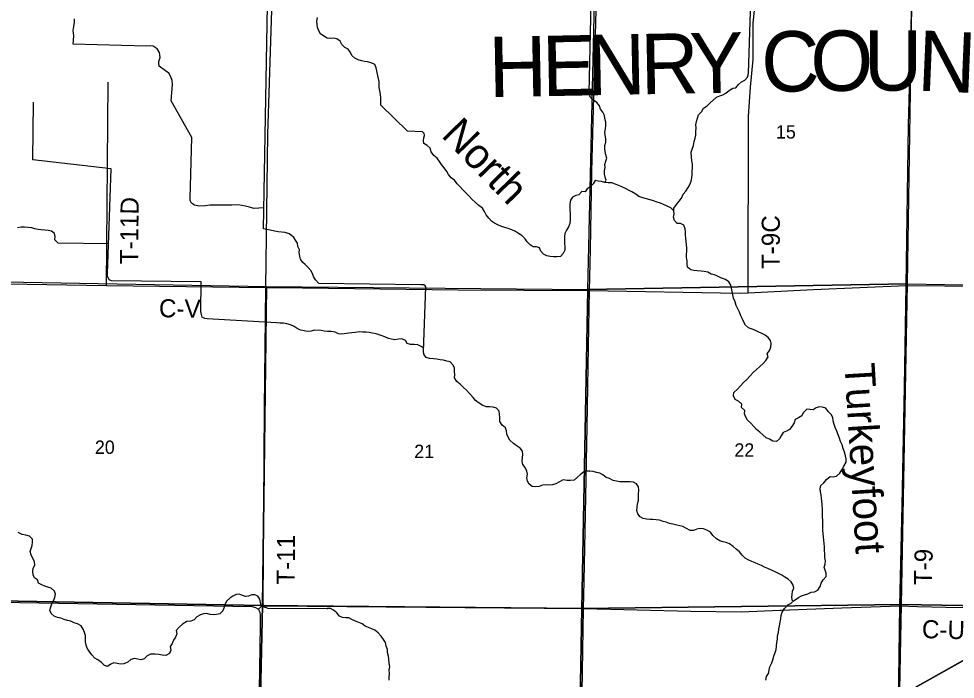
# Model space of a CAD drawing. Extents: x -6.2 to 37.4, y 0.2 to 22.2.
# Drawn here: x 3.568 to 5.038, y 19.239 to 20.275 of the extents above; entities that cross this region are included whole.
import ezdxf

# ---------------------------------------------------------------- set-up
doc = ezdxf.new("R2010")
doc.units = 0
for name, color, linetype in [('GM_X_County_Road', 7, 'Continuous'), ('GM_X_County_Road_Text', 7, 'Continuous'), ('GM_X_County_Text', 7, 'Continuous'), ('GM_X_Minor_River', 7, 'Continuous'), ('GM_X_Minor_River_Text', 7, 'Continuous'), ('GM_X_Section', 7, 'Continuous'), ('GM_X_Section_Text', 7, 'Continuous'), ('GM_X_Township_Road', 7, 'Continuous'), ('GM_X_Township_Road_Text', 7, 'Continuous'), ('SH_Border', 7, 'Continuous'), ('SH_Data', 7, 'Continuous')]:
    doc.layers.add(name, color=color, linetype=linetype)

msp = doc.modelspace()

# ---------------------------------------------------------------- linework, layer by layer
at = {"layer": 'GM_X_County_Road'}
for points in [[(2.9584, 19.8774), (3.2306, 19.8655), (3.4561, 19.861), (3.7061, 19.8569), (3.956, 19.8537), (3.9729, 19.8535), (4.2583, 19.8498), (4.4643, 19.8487)], [(4.4643, 19.8487), (4.6989, 19.8446), (4.7131, 19.8453), (4.8157, 19.8502), (4.9612, 19.8569), (5.0809, 19.8554)], [(4.9421, 18.8443), (4.9484, 19.1615), (4.9514, 19.3541)], [(4.9514, 19.3541), (4.9789, 19.3528), (5.0234, 19.3518), (5.0805, 19.3507), (5.0809, 19.3507)]]:
    msp.add_lwpolyline(points, dxfattribs=at)
at = {"layer": 'GM_X_Minor_River'}
for points in [[(4.2038, 19.7539), (4.2074, 19.8544), (4.2061, 19.8561), (4.2041, 19.8575), (4.1997, 19.8578), (4.0393, 19.8599), (4.0339, 19.8657), (4.0308, 19.871), (4.0292, 19.8756), (4.0266, 19.8804), (4.0224, 19.8851), (4.0177, 19.8895), (4.0144, 19.8928), (4.0107, 19.8982), (4.0093, 19.9024), (4.0087, 19.9091), (4.0088, 19.9128), (4.0066, 19.918), (4.0061, 19.9233), (4.0026, 19.9278), (3.9999, 19.932), (3.9967, 19.9353), (3.9926, 19.9376), (3.9864, 19.9397), (3.9755, 19.941), (3.9527, 19.9458), (3.9597, 20.3549)], [(4.4634, 20.1588), (4.468, 20.348)], [(4.7137, 20.1892), (4.719, 20.3522)], [(3.9532, 19.9785), (3.9376, 19.9775), (3.9307, 19.9795), (3.9243, 19.9809), (3.9129, 19.9831), (3.9029, 19.9827), (3.8912, 19.9826), (3.8792, 19.9826), (3.8681, 19.9826), (3.8616, 19.9818), (3.8514, 19.9809), (3.844, 19.9827), (3.8396, 19.9857), (3.8376, 19.9901), (3.8373, 19.9933), (3.84, 20.0887), (3.8077, 20.1464), (3.8096, 20.1718), (3.809, 20.1781), (3.8072, 20.184), (3.8037, 20.1896), (3.7985, 20.1937), (3.7888, 20.2009), (3.7883, 20.2053), (3.7884, 20.2079), (3.7904, 20.2143), (3.7894, 20.2225), (3.7858, 20.2281), (3.7796, 20.232), (3.7736, 20.2329), (3.7681, 20.232), (3.654, 20.2355), (3.6545, 20.2415), (3.6547, 20.2483), (3.6539, 20.2567), (3.6546, 20.263), (3.6559, 20.2696), (3.656, 20.2753)], [(4.1294, 20.1984), (4.1271, 20.2032), (4.1216, 20.2059), (4.116, 20.2074), (4.1111, 20.2079), (4.1062, 20.2091), (4.1013, 20.2105), (4.0961, 20.2131), (4.091, 20.2174), (4.0889, 20.2223), (4.0852, 20.2277), (4.0803, 20.2299), (4.0755, 20.235), (4.0731, 20.2399), (4.0677, 20.2438), (4.0626, 20.2445), (4.0572, 20.2444), (4.0522, 20.2449), (4.047, 20.2477), (4.0418, 20.2518), (4.0392, 20.2565), (4.0373, 20.2615), (4.0366, 20.2668), (4.0361, 20.2716), (4.0374, 20.2773)], [(4.2037, 20.0844), (4.2039, 20.0885), (4.205, 20.0921), (4.2045, 20.095), (4.2036, 20.0963), (4.2019, 20.0979), (4.1783, 20.0986), (4.1367, 20.1396), (4.1366, 20.1504), (4.136, 20.1569), (4.1343, 20.1674), (4.1343, 20.1763), (4.1294, 20.1984)], [(4.5964, 19.9738), (4.5967, 19.978), (4.6006, 19.984), (4.6051, 19.989), (4.6086, 19.9939), (4.6113, 19.9999), (4.6154, 20.0049), (4.6191, 20.0102), (4.6217, 20.0154), (4.6235, 20.0205), (4.6249, 20.0254), (4.6254, 20.0305), (4.6253, 20.0356), (4.6258, 20.0415), (4.626, 20.0472), (4.6249, 20.0525), (4.6245, 20.0579), (4.6239, 20.0658), (4.6255, 20.0707), (4.6275, 20.0764), (4.6286, 20.0826), (4.6302, 20.0879), (4.6311, 20.0928), (4.6312, 20.0983), (4.6315, 20.104), (4.6312, 20.1087), (4.6323, 20.1142), (4.6335, 20.1191), (4.6355, 20.1242), (4.64, 20.1294), (4.6431, 20.1347), (4.6487, 20.1386), (4.6537, 20.1434), (4.6637, 20.1523), (4.6689, 20.1541), (4.6737, 20.1559), (4.6784, 20.1584), (4.6837, 20.1629), (4.689, 20.1662), (4.6938, 20.1667), (4.698, 20.1721), (4.7029, 20.176), (4.7078, 20.1787), (4.7123, 20.1836), (4.7137, 20.1892)], [(4.4883, 20.0185), (4.4901, 20.0219), (4.4889, 20.0268), (4.4877, 20.0316), (4.4878, 20.0365), (4.4886, 20.0418), (4.4885, 20.0466), (4.4896, 20.0519), (4.4916, 20.0567), (4.4896, 20.0619), (4.4886, 20.0669), (4.4881, 20.0718), (4.488, 20.0765), (4.49, 20.0816), (4.4896, 20.0866), (4.4887, 20.0925), (4.4881, 20.0972), (4.4891, 20.1025), (4.4898, 20.1076), (4.4899, 20.1131), (4.4885, 20.1186), (4.4877, 20.1236), (4.4853, 20.1284), (4.4816, 20.1334), (4.4797, 20.1384), (4.4756, 20.1436), (4.4706, 20.1475), (4.4656, 20.1519), (4.4638, 20.1569), (4.4634, 20.1588)], [(3.9729, 19.7982), (3.8642, 19.8044), (3.8602, 19.8051), (3.8561, 19.8068), (3.855, 19.811), (3.8542, 19.8158), (3.8548, 19.8623), (3.7138, 19.8638), (3.7104, 19.8657), (3.7079, 19.8713), (3.7078, 19.8755), (3.7133, 20.0398), (3.5904, 20.0539), (3.5913, 20.1443)], [(4.4574, 20.0038), (4.4524, 20.0044), (4.4474, 19.9988), (4.4425, 19.998), (4.4373, 19.9954), (4.4342, 19.9904), (4.4333, 19.9849), (4.4332, 19.9798), (4.4335, 19.975), (4.4336, 19.9703), (4.434, 19.965), (4.4337, 19.9595), (4.4332, 19.954), (4.4314, 19.9485), (4.4281, 19.9436), (4.4255, 19.9384), (4.4248, 19.9331), (4.4247, 19.9282), (4.4252, 19.9228), (4.4254, 19.9173), (4.4255, 19.912), (4.4228, 19.9071), (4.4185, 19.9023), (4.4128, 19.9017), (4.4079, 19.9018), (4.4024, 19.9021), (4.3971, 19.9033), (4.3919, 19.9057), (4.388, 19.9107), (4.3859, 19.916), (4.381, 19.9175), (4.376, 19.9174), (4.371, 19.9203), (4.3666, 19.9252), (4.3631, 19.93), (4.3582, 19.935), (4.3526, 19.9382), (4.3478, 19.9413), (4.3422, 19.9441), (4.3363, 19.9463), (4.3311, 19.9479), (4.3258, 19.9493), (4.3204, 19.9521), (4.3153, 19.9547), (4.3103, 19.9576), (4.306, 19.9624), (4.3018, 19.9676), (4.2992, 19.9726), (4.2961, 19.978), (4.2907, 19.9823), (4.285, 19.9871), (4.2794, 19.992), (4.2751, 19.997), (4.2707, 20.0018), (4.2653, 20.0067), (4.2614, 20.0115), (4.2564, 20.0164), (4.2524, 20.0219), (4.2471, 20.0258), (4.2431, 20.0307), (4.2402, 20.0357), (4.2361, 20.0411), (4.2317, 20.0465), (4.2286, 20.0514), (4.2253, 20.0563), (4.2201, 20.0609), (4.2156, 20.0665), (4.214, 20.0719), (4.2092, 20.0761), (4.2044, 20.0793), (4.2037, 20.0844)], [(4.7124, 19.6454), (4.7093, 19.6502), (4.7075, 19.6552), (4.7081, 19.6605), (4.7029, 19.6655), (4.7032, 19.6704), (4.6978, 19.6751), (4.6926, 19.678), (4.6903, 19.6834), (4.6908, 19.6889), (4.6964, 19.6941), (4.7012, 19.6993), (4.7058, 19.7043), (4.7109, 19.709), (4.7161, 19.7149), (4.7208, 19.7202), (4.7258, 19.7244), (4.7314, 19.7296), (4.7368, 19.7342), (4.7412, 19.7391), (4.7447, 19.7445), (4.7431, 19.7497), (4.7465, 19.7545), (4.749, 19.7598), (4.7491, 19.7655), (4.7485, 19.7702), (4.7446, 19.7751), (4.7398, 19.7788), (4.7345, 19.7813), (4.7291, 19.7841), (4.7238, 19.7865), (4.7137, 19.7905), (4.7089, 19.7944), (4.7065, 19.7992), (4.7043, 19.8039), (4.7016, 19.8093), (4.6994, 19.8147), (4.6971, 19.8202), (4.6944, 19.8252), (4.6928, 19.8309), (4.6903, 19.837), (4.6889, 19.8418), (4.688, 19.8475), (4.6872, 19.8525), (4.6861, 19.8572), (4.6827, 19.8622), (4.6774, 19.866), (4.6716, 19.868), (4.6651, 19.8715), (4.6602, 19.8733), (4.6553, 19.8746), (4.6499, 19.8775), (4.6444, 19.8788), (4.6395, 19.8794), (4.6334, 19.8797), (4.628, 19.8802), (4.6231, 19.8813), (4.6182, 19.8852), (4.6174, 19.8903), (4.6173, 19.8954), (4.6166, 19.9008), (4.617, 19.9154), (4.6163, 19.9212), (4.6154, 19.9308), (4.6151, 19.9361), (4.6148, 19.9408), (4.6144, 19.9458), (4.612, 19.9511), (4.6072, 19.9541), (4.6017, 19.954), (4.5976, 19.9588), (4.5962, 19.9641), (4.5971, 19.9691), (4.5964, 19.9738), (4.5916, 19.9787), (4.5862, 19.9814), (4.5805, 19.9838), (4.5757, 19.9858), (4.5704, 19.9876), (4.5646, 19.9896), (4.5593, 19.9909), (4.5536, 19.9925), (4.5478, 19.9941), (4.5418, 19.9964), (4.537, 19.9999), (4.5308, 20.0036), (4.5255, 20.0065), (4.5205, 20.0091), (4.5151, 20.0117), (4.51, 20.0137), (4.5047, 20.0159), (4.4995, 20.0177), (4.4936, 20.018), (4.4883, 20.0185), (4.4829, 20.0197), (4.478, 20.0204), (4.4729, 20.0213), (4.4701, 20.0162), (4.4653, 20.0116), (4.4605, 20.0086), (4.4574, 20.0038)], [(3.6301, 19.9233), (3.6252, 19.9283), (3.6253, 19.9336), (3.6245, 19.9384), (3.6197, 19.9421), (3.6144, 19.9432), (3.6095, 19.9433), (3.6038, 19.9439), (3.5989, 19.9444), (3.5936, 19.9458), (3.5887, 19.9469), (3.5834, 19.9476), (3.5774, 19.9484), (3.5721, 19.9484), (3.5664, 19.947)], [(3.7094, 19.9223), (3.6301, 19.9233)], [(4.204, 19.7586), (4.2002, 19.7612), (4.1947, 19.7636), (4.1892, 19.7641), (4.1832, 19.764), (4.1781, 19.7655), (4.1754, 19.7704), (4.1694, 19.773), (4.1644, 19.7724), (4.1589, 19.7715), (4.1535, 19.7724), (4.1485, 19.7733), (4.1431, 19.776), (4.1373, 19.7782), (4.1292, 19.7807), (4.1237, 19.7819), (4.1185, 19.7828), (4.1136, 19.7836), (4.1079, 19.7834), (4.103, 19.784), (4.0963, 19.7827), (4.0912, 19.7826), (4.0863, 19.7819), (4.0753, 19.7802), (4.07, 19.7811), (4.0651, 19.7833), (4.0589, 19.7844), (4.053, 19.7847), (4.0479, 19.7848), (4.043, 19.7862), (4.0322, 19.7864), (4.0275, 19.7848), (4.0214, 19.7847), (4.0163, 19.7854), (4.0107, 19.7867), (4.0056, 19.7892), (4.0004, 19.7924), (3.9949, 19.7948), (3.9893, 19.7966), (3.9838, 19.7976), (3.9781, 19.7977), (3.9729, 19.7982)], [(4.3589, 19.5867), (4.3596, 19.5916), (4.3591, 19.5966), (4.3552, 19.6016), (4.3504, 19.6045), (4.345, 19.6086), (4.339, 19.6139), (4.3365, 19.6187), (4.3345, 19.6234), (4.3338, 19.6286), (4.3322, 19.6335), (4.3272, 19.6376), (4.3236, 19.6434), (4.3237, 19.6498), (4.323, 19.6548), (4.3222, 19.6595), (4.3183, 19.6644), (4.3129, 19.666), (4.3078, 19.6663), (4.3023, 19.6662), (4.297, 19.6684), (4.2908, 19.6719), (4.2853, 19.676), (4.2814, 19.6809), (4.276, 19.6874), (4.271, 19.6924), (4.2662, 19.6967), (4.261, 19.7017), (4.256, 19.7058), (4.2521, 19.7116), (4.2526, 19.7165), (4.2523, 19.7218), (4.2522, 19.7268), (4.2503, 19.7317), (4.2456, 19.7368), (4.2402, 19.7382), (4.2349, 19.7395), (4.2296, 19.7401), (4.2245, 19.7412), (4.2191, 19.7417), (4.2132, 19.7424), (4.2076, 19.7438), (4.2039, 19.7488), (4.2038, 19.7539)], [(4.7608, 19.3121), (4.7615, 19.3178), (4.7622, 19.3229), (4.7635, 19.3286), (4.7643, 19.3335), (4.7652, 19.3391), (4.7668, 19.3442), (4.7705, 19.35), (4.7756, 19.3556), (4.7806, 19.3584), (4.7856, 19.3622), (4.7923, 19.3674), (4.7971, 19.3698), (4.8018, 19.3716), (4.807, 19.373), (4.8119, 19.3754), (4.8171, 19.376), (4.8224, 19.3788), (4.826, 19.3846), (4.828, 19.3897), (4.8309, 19.3947), (4.8356, 19.4003), (4.8357, 19.4052), (4.8341, 19.41), (4.8323, 19.4148), (4.8339, 19.4197), (4.8346, 19.4246), (4.8337, 19.4299), (4.8333, 19.4354), (4.8328, 19.4413), (4.8329, 19.4466), (4.8323, 19.4518), (4.8318, 19.4571), (4.8314, 19.462), (4.8309, 19.4675), (4.8305, 19.4725), (4.8302, 19.4776), (4.8303, 19.4829), (4.8302, 19.488), (4.8301, 19.4939), (4.8299, 19.4992), (4.8298, 19.504), (4.8292, 19.5135), (4.8288, 19.5182), (4.8281, 19.523), (4.8276, 19.5281), (4.8268, 19.5329), (4.8261, 19.5378), (4.8274, 19.5429), (4.8322, 19.5472), (4.8363, 19.5522), (4.8417, 19.5572), (4.8468, 19.5564), (4.8517, 19.5576), (4.8571, 19.5624), (4.8601, 19.5677), (4.8634, 19.5733), (4.8671, 19.5793), (4.8671, 19.5846), (4.8662, 19.5896), (4.8646, 19.5953), (4.8625, 19.6008), (4.8605, 19.6066), (4.8582, 19.6121), (4.8566, 19.6173), (4.8544, 19.6226), (4.8523, 19.6283), (4.8499, 19.6337), (4.8483, 19.6387), (4.8467, 19.6444), (4.8463, 19.6497), (4.8437, 19.6545), (4.8387, 19.659), (4.8352, 19.6644), (4.83, 19.6656), (4.825, 19.6663), (4.8201, 19.665), (4.8151, 19.6615), (4.8102, 19.6622), (4.8051, 19.6629), (4.7995, 19.6569), (4.7975, 19.652), (4.7923, 19.6489), (4.7872, 19.6464), (4.7853, 19.6411), (4.782, 19.6356), (4.7781, 19.6306), (4.7733, 19.6282), (4.7684, 19.6259), (4.765, 19.6208), (4.7623, 19.6159), (4.7575, 19.6117), (4.7518, 19.6124), (4.7468, 19.6157), (4.7415, 19.6179), (4.7363, 19.6225), (4.7313, 19.6268), (4.7265, 19.6309), (4.7222, 19.6357), (4.7172, 19.6407), (4.7124, 19.6454)], [(4.7827, 19.3619), (4.7819, 19.3669), (4.7822, 19.372), (4.7828, 19.3769), (4.7848, 19.3818), (4.784, 19.3867), (4.7809, 19.3916), (4.7759, 19.396), (4.7706, 19.3992), (4.7658, 19.4021), (4.7609, 19.4047), (4.7555, 19.4072), (4.7498, 19.4102), (4.744, 19.4124), (4.739, 19.4148), (4.7339, 19.4172), (4.729, 19.4193), (4.724, 19.4215), (4.7191, 19.4237), (4.7142, 19.4257), (4.7086, 19.429), (4.7038, 19.4337), (4.6995, 19.4387), (4.6945, 19.4432), (4.6895, 19.4473), (4.6841, 19.4514), (4.6788, 19.4532), (4.6739, 19.4546), (4.6687, 19.4562), (4.6636, 19.4592), (4.6577, 19.4646), (4.654, 19.4696), (4.6484, 19.4729), (4.6431, 19.4748), (4.6376, 19.4754), (4.6325, 19.4744), (4.6274, 19.4722), (4.6221, 19.4725), (4.6108, 19.4784), (4.6059, 19.4795), (4.601, 19.4809), (4.595, 19.482), (4.5897, 19.4832), (4.5847, 19.4856), (4.5796, 19.4863), (4.5739, 19.4885), (4.5688, 19.4888), (4.5637, 19.4898), (4.5588, 19.4894), (4.5535, 19.4902), (4.5484, 19.4913), (4.5436, 19.4938), (4.5401, 19.4986), (4.5385, 19.5034), (4.539, 19.5087), (4.5397, 19.5142), (4.5411, 19.5191), (4.5413, 19.5294), (4.5416, 19.5356), (4.5413, 19.5407), (4.5382, 19.5455), (4.5334, 19.5481), (4.5281, 19.5486), (4.5228, 19.5485), (4.5177, 19.5486), (4.512, 19.5489), (4.5067, 19.5496), (4.5014, 19.5508), (4.4954, 19.5538), (4.4902, 19.5556), (4.4851, 19.5597), (4.4803, 19.5623), (4.4754, 19.5635), (4.4699, 19.5646), (4.4648, 19.5654), (4.4599, 19.5655), (4.4551, 19.5641), (4.4501, 19.5604), (4.4453, 19.5558), (4.4401, 19.5513), (4.4346, 19.5505), (4.4293, 19.5506), (4.4229, 19.5518), (4.417, 19.5484), (4.4114, 19.5454), (4.4063, 19.5438), (4.4006, 19.5432), (4.3953, 19.5437), (4.3902, 19.5432), (4.3852, 19.5414), (4.3795, 19.5406), (4.3742, 19.5413), (4.3694, 19.5452), (4.3668, 19.5499), (4.366, 19.5547), (4.3669, 19.5606), (4.3658, 19.5655), (4.3633, 19.5711), (4.3596, 19.5759), (4.3584, 19.581), (4.3589, 19.5867)], [(3.5878, 19.4342), (3.5862, 19.4391), (3.5878, 19.444), (3.5893, 19.4489), (3.5901, 19.4538), (3.5899, 19.4586), (3.585, 19.4636), (3.5794, 19.4651), (3.5737, 19.4659), (3.5677, 19.4691)], [(3.9586, 19.3505), (3.9537, 19.3521), (3.9488, 19.3543), (3.9476, 19.3592), (3.9466, 19.3644), (3.9438, 19.3694), (3.9389, 19.3715), (3.934, 19.3713), (3.9292, 19.3693), (3.9243, 19.3686), (3.9194, 19.3704), (3.9144, 19.3726), (3.9096, 19.3718), (3.9046, 19.3692), (3.8995, 19.3663), (3.8946, 19.3616), (3.8924, 19.3567), (3.891, 19.3518), (3.8886, 19.3464), (3.8838, 19.3415), (3.8789, 19.3405), (3.8741, 19.34), (3.8686, 19.3405), (3.8634, 19.3423), (3.8586, 19.3417), (3.8535, 19.3401), (3.8479, 19.337), (3.8437, 19.3321), (3.8385, 19.3299), (3.8324, 19.3293), (3.8254, 19.3251), (3.8203, 19.3204), (3.8157, 19.3154), (3.8163, 19.3099), (3.8143, 19.305), (3.8114, 19.3001), (3.809, 19.2952), (3.8059, 19.2902), (3.8069, 19.2843), (3.8049, 19.2792), (3.799, 19.2759), (3.7933, 19.2766), (3.7882, 19.2776), (3.7827, 19.2781), (3.7752, 19.2781), (3.7698, 19.2757), (3.7652, 19.2709), (3.76, 19.2695), (3.7551, 19.2705), (3.7502, 19.2714), (3.7445, 19.27), (3.7397, 19.2657), (3.7332, 19.263), (3.7279, 19.2627), (3.7228, 19.2638), (3.7177, 19.2645), (3.7128, 19.2625), (3.7078, 19.2588), (3.7029, 19.2606), (3.698, 19.2652), (3.6926, 19.2695), (3.6876, 19.2721), (3.6833, 19.2771), (3.6791, 19.2827), (3.676, 19.2877), (3.6742, 19.2926), (3.673, 19.2976), (3.6732, 19.3074), (3.6716, 19.3124), (3.6696, 19.3176), (3.6665, 19.3226), (3.6605, 19.3259), (3.6552, 19.3272), (3.65, 19.3299), (3.6451, 19.3312), (3.6398, 19.3328), (3.6344, 19.3346), (3.6293, 19.3358), (3.6242, 19.338), (3.6194, 19.3419), (3.6174, 19.3475), (3.6185, 19.3524), (3.6205, 19.3573), (3.623, 19.3621), (3.6249, 19.3674), (3.6259, 19.3723), (3.6247, 19.3773), (3.6193, 19.3816), (3.6142, 19.3832), (3.6093, 19.3852), (3.6044, 19.387), (3.5996, 19.3899), (3.598, 19.3951), (3.5931, 19.3978), (3.5908, 19.4028), (3.5905, 19.4083), (3.5912, 19.4132), (3.5937, 19.4181), (3.5929, 19.4238), (3.5902, 19.4294), (3.5878, 19.4342)], [(3.9586, 19.3505), (4.0526, 19.3501)], [(4.0674, 19.3432), (4.0626, 19.3472), (4.0577, 19.3498), (4.0526, 19.3501), (4.0534, 19.3501)], [(4.15, 19.2376), (4.1495, 19.2425), (4.1502, 19.2476), (4.1498, 19.2535), (4.1506, 19.2584), (4.1496, 19.2636), (4.1494, 19.2702), (4.1489, 19.2753), (4.1473, 19.281), (4.147, 19.2858), (4.1453, 19.2906), (4.144, 19.2963), (4.1411, 19.3015), (4.1374, 19.3065), (4.1323, 19.3115), (4.1274, 19.3158), (4.1225, 19.318), (4.1175, 19.32), (4.112, 19.322), (4.1072, 19.3257), (4.1021, 19.328), (4.0969, 19.3302), (4.0914, 19.3326), (4.0866, 19.3352), (4.0815, 19.3355), (4.0765, 19.3356), (4.0717, 19.338), (4.0674, 19.3432)], [(4.7407, 19.2376), (4.7422, 19.2431), (4.7449, 19.2479), (4.7474, 19.2585), (4.7502, 19.2645), (4.752, 19.2696), (4.7536, 19.2753), (4.7556, 19.2807), (4.7571, 19.2856), (4.7577, 19.2909), (4.7582, 19.2964), (4.7593, 19.3017), (4.759, 19.3068), (4.7608, 19.3121)]]:
    msp.add_lwpolyline(points, dxfattribs=at)
at = {"layer": 'GM_X_Section'}
for points in [[(4.4733, 20.347), (4.7305, 20.3504), (4.9704, 20.3624), (4.963, 19.8591), (4.4615, 19.8502)], [(3.9572, 19.8551), (3.9512, 19.3544), (3.4485, 19.3634), (3.4579, 19.8638)], [(4.963, 19.8591), (4.9531, 19.3564), (4.4522, 19.3499), (4.4615, 19.8502)], [(4.4615, 19.8502), (4.4522, 19.3499), (3.9512, 19.3544), (3.9572, 19.8551)], [(3.4485, 19.3634), (3.9512, 19.3544), (3.9401, 18.8573), (3.4402, 18.8631)], [(3.9512, 19.3544), (4.4522, 19.3499), (4.4434, 18.8501), (3.9401, 18.8573)], [(4.4522, 19.3499), (4.9531, 19.3564), (4.9435, 18.8467), (4.4434, 18.8501)]]:
    msp.add_lwpolyline(points, close=True, dxfattribs=at)
for points in [[(5.0809, 19.3541), (4.9531, 19.3564), (4.963, 19.8591), (5.0809, 19.857)], [(5.0809, 18.8458), (4.9435, 18.8467), (4.9531, 19.3564), (5.0809, 19.3541)]]:
    msp.add_lwpolyline(points, dxfattribs=at)
at = {"layer": 'GM_X_Township_Road'}
for p, q in [((3.7061, 19.8569), (3.7087, 20.1759)), ((3.9449, 19.3486), (3.952, 19.3564))]:
    msp.add_line(p, q, dxfattribs=at)
for points in [[(4.9612, 19.8569), (4.9647, 20.1084), (4.9718, 20.3625)], [(3.952, 19.3564), (3.9541, 19.6636), (3.956, 19.8537), (3.9591, 20.0942), (3.9676, 20.3538)], [(4.4643, 19.8487), (4.4656, 19.9134), (4.4678, 20.0349), (4.4694, 20.0951), (4.4761, 20.3474)], [(4.7131, 19.8453), (4.7139, 20.1219), (4.7168, 20.1676), (4.721, 20.2115), (4.7211, 20.2687), (4.73, 20.3515)], [(4.4458, 18.8505), (4.4481, 18.9821), (4.4513, 19.134), (4.4523, 19.1854), (4.4549, 19.3499), (4.4556, 19.3926), (4.4577, 19.4978), (4.4606, 19.6355), (4.463, 19.7913), (4.4643, 19.8487)], [(4.9514, 19.3541), (4.9551, 19.5116), (4.9586, 19.6975), (4.9612, 19.8569)], [(3.4477, 19.3613), (3.9345, 19.3529), (3.9398, 19.3513), (3.9449, 19.3486)], [(3.9385, 18.8541), (3.9454, 19.1535), (3.9478, 19.3231), (3.9478, 19.3406), (3.9473, 19.3436), (3.9449, 19.3486)], [(3.952, 19.3564), (3.9547, 19.3541), (3.9591, 19.354), (4.4549, 19.3499)], [(4.4549, 19.3499), (4.6232, 19.3455), (4.7021, 19.3448), (4.7634, 19.3472), (4.7644, 19.3473)], [(4.7644, 19.3473), (4.8604, 19.3512), (4.9514, 19.3541)]]:
    msp.add_lwpolyline(points, dxfattribs=at)
at = {"layer": 'SH_Border'}
msp.add_line((2.4803, 17.8272), (9.0866, 21.532), dxfattribs=at)
at = {"layer": 'SH_Data'}
msp.add_lwpolyline([(9.0866, 21.3538), (2.4803, 17.8272), (9.0866, 21.532)], close=True, dxfattribs=at)

# ---------------------------------------------------------------- texts
at = {"layer": 'GM_X_County_Road_Text'}
for s, rotation, p in [('C-V', 359.2047, (3.7883, 19.8069)), ('C-U', 358.4087, (4.9856, 19.3035))]:
    msp.add_text(s, height=0.02841, rotation=rotation, dxfattribs=at).set_placement(p)
at = {"layer": 'GM_X_County_Text'}
for s, rotation, p in [('C', 0.9948, (4.7345, 20.1602)), ('O', 0.6873, (4.8115, 20.1615)), ('U', 0, (4.8949, 20.1625)), ('N', 357.5809, (4.9776, 20.1625)), ('H', 1.0973, (4.3067, 20.152)), ('E', 1.0968, (4.3905, 20.1536)), ('N', 1.0962, (4.4613, 20.155)), ('R', 1.0971, (4.545, 20.1566)), ('Y', 1.0918, (4.6221, 20.158))]:
    msp.add_text(s, height=0.0947, rotation=rotation, dxfattribs=at).set_placement(p)
at = {"layer": 'GM_X_Minor_River_Text'}
for s, rotation, p in [('North', 314.2975, (4.2299, 20.0911)), ('Turkeyfoot', 273.4318, (4.8643, 19.7337))]:
    msp.add_text(s, height=0.04738, rotation=rotation, dxfattribs=at).set_placement(p)
at = {"layer": 'GM_X_Section_Text'}
for s, p in [('15', (4.7569, 20.0873)), ('20', (3.6879, 19.5925)), ('22', (4.6916, 19.5881)), ('21', (4.1891, 19.586))]:
    msp.add_text(s, height=0.02093, rotation=0, dxfattribs=at).set_placement(p)
at = {"layer": 'GM_X_Township_Road_Text'}
for s, rotation, p in [('T-11D', 89.4841, (3.7557, 19.8899)), ('T-9C', 90, (4.7629, 19.8825)), ('T-11', 89.6465, (4.0016, 19.3872)), ('T-9', 88.5668, (5.0016, 19.3862))]:
    msp.add_text(s, height=0.02841, rotation=rotation, dxfattribs=at).set_placement(p)

doc.saveas('drawing.dxf')
